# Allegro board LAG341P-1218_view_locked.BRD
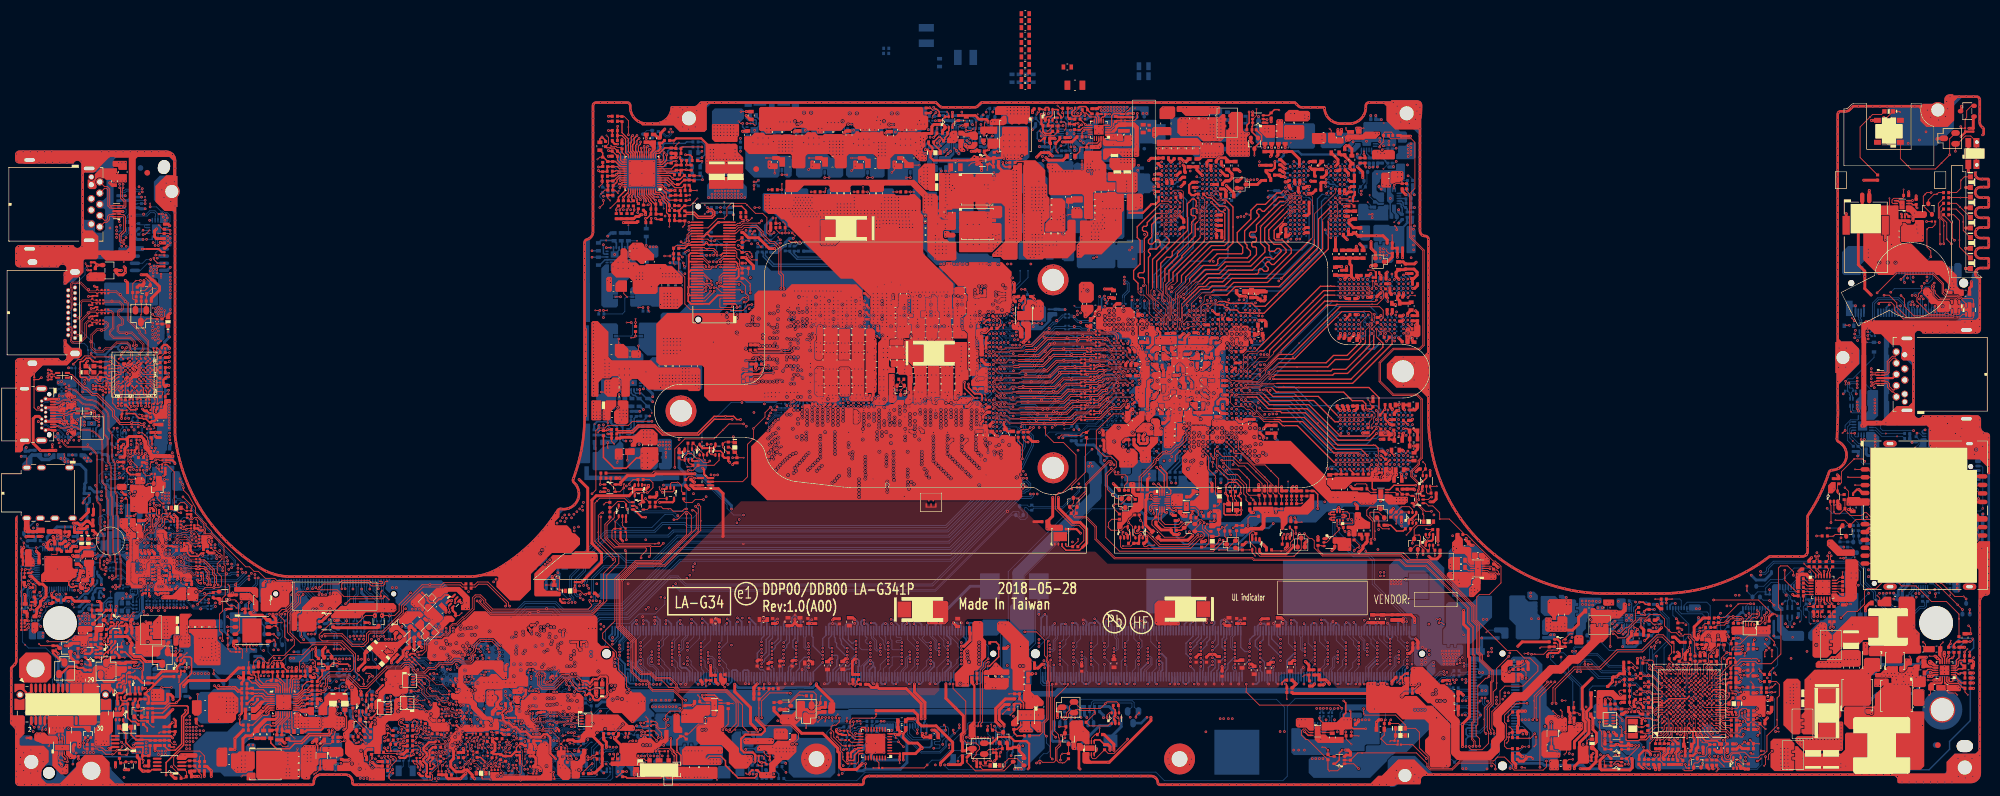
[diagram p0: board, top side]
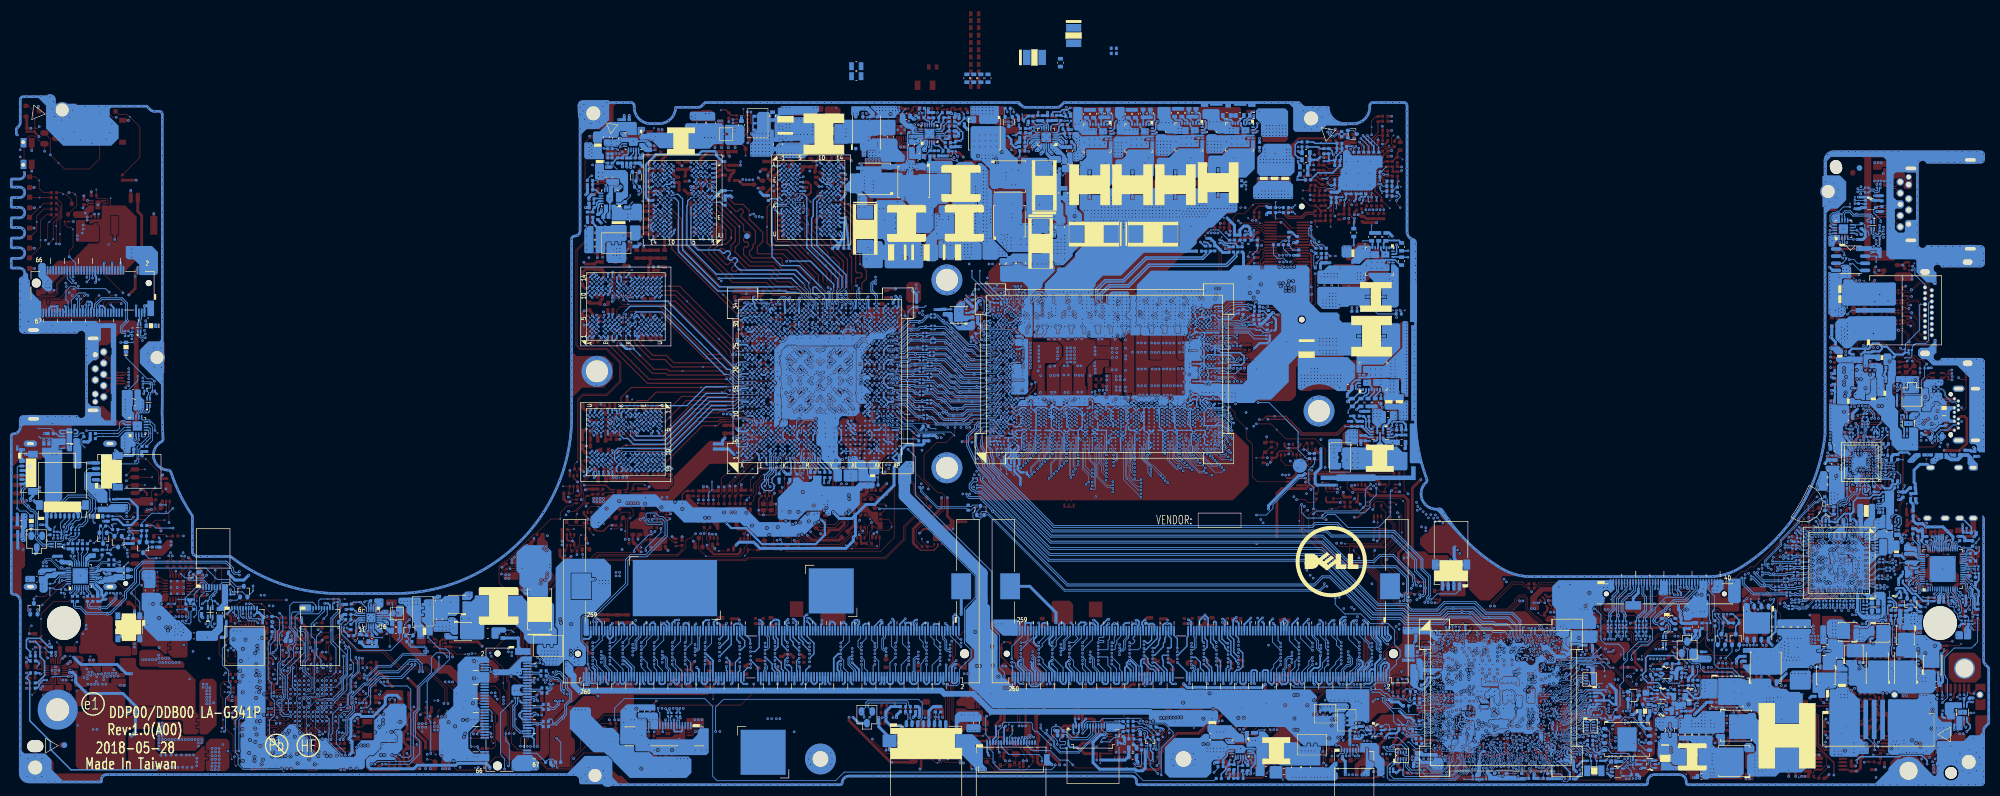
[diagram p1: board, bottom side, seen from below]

No outline. copper layers: TOP, GND1, IN1, IN2, GND2, IN3, IN4, VCC, IN5, IN6, GND3, BOTTOM. Coordinates in mm from the lowest, leftmost part position.

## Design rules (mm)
net group DDI1: nets DDI1_DDPB_CTRLCLK DDI1_DDPB_CTRLDAT
net group DDI2: nets DDI2_DDPC_CTRLCLK DDI2_DDPC_CTRLDAT
net group GPU-SENSE: nets VCCSENSE_VGA VSSSENSE_VGA
net group HDMI-DDC: nets DDC_CLK_HDMI DDC_DAT_HDMI
net group LPC_CLK: nets PCI_CLK_LPC1 PCI_CLK_LPC1_R
net group SENSE: nets VCC_SENSE VSS_SENSE
net group TBT_RX/TX: nets TBT_USB3_TX0_N_C TBT_USB3_TX1_N_C
net group UART: nets UART2_RXD UART2_TXD
net group USB3.0-TBTA: nets TBTA_CC1 TBTA_CC2
net group ASY: nets CPU_TRIGGER CPU_TRIGGER_R DGPU_HOLD_RST# H_CATERR# H_CPUPWRGD H_PM_DOWN H_PM_DOWN_R H_PM_SYNC H_PM_SYNC_R H_PROCHOT# H_PROCHOT#_EC H_PROCHOT#_R H_THERMTRIP# H_THERMTRIP#_R H_VCCST_PWRGD INTRUDER# LPC_PD# PCH_DPWROK_EC PCH_DPWROK_R PCH_PCIE_WAKE# PCH_PWROK PCH_RSMRST# PCH_SYS_PWROK_XDP PCH_TRIGGER PCH_TRIGGER_R PLTRST_CPU# PWRBTN#_XDP SIO_PWRBTN# SIO_RCIN# SYS_PWROK SYS_RESET# VCCST_PWRGD_CPU XDP_BPM#0 XDP_BPM#1
net group AUDIO: nets HPOUT_D_L_C HPOUT_D_R_C HPOUT_L HPOUT_L_R1 HPOUT_R HPOUT_R_R2 LINE1-VREFO LINE1_L LINE1_L_C LINE1_R LINE1_R_C MIC1-VREFO_L MIC1-VREFO_R RING2 RING2_L SLEEVE SLEEVE_L
net group DDR_CLK: nets M_CLK_DDR0 M_CLK_DDR1 M_CLK_DDR2 M_CLK_DDR3 M_CLK_DDR#0 M_CLK_DDR#1 M_CLK_DDR#2 M_CLK_DDR#3
net group DDR_DQS: nets DDR_A_DQS0 DDR_A_DQS1 DDR_A_DQS2 DDR_A_DQS3 DDR_A_DQS4 DDR_A_DQS5 DDR_A_DQS6 DDR_A_DQS7 DDR_A_DQS#0 DDR_A_DQS#1 DDR_A_DQS#2 DDR_A_DQS#3 DDR_A_DQS#4 DDR_A_DQS#5 DDR_A_DQS#6 DDR_A_DQS#7 DDR_B_DQS0 DDR_B_DQS1 DDR_B_DQS2 DDR_B_DQS3 DDR_B_DQS4 DDR_B_DQS5 DDR_B_DQS6 DDR_B_DQS7 DDR_B_DQS#0 DDR_B_DQS#1 DDR_B_DQS#2 DDR_B_DQS#3 DDR_B_DQS#4 DDR_B_DQS#5 DDR_B_DQS#6 DDR_B_DQS#7
net group DDRA_ADD: nets DDR_A_ACT# DDR_A_ALERT# DDR_A_BG0 DDR_A_BG1 DDR_A_BS0 DDR_A_BS1 DDR_A_CAS# DDR_A_MA0 DDR_A_MA1 DDR_A_MA2 DDR_A_MA3 DDR_A_MA4 DDR_A_MA5 DDR_A_MA6 DDR_A_MA7 DDR_A_MA8 DDR_A_MA9 DDR_A_MA10 DDR_A_MA11 DDR_A_MA12 DDR_A_MA13 DDR_A_PAR DDR_A_RAS# DDR_A_WE#
net group DDRA_CTRL: nets DDR_CKE0_DIMMA DDR_CKE1_DIMMA DDR_CS0_DIMMA# DDR_CS1_DIMMA# M_ODT0 M_ODT1
net group DDRA_D0: nets DDR_A_D0 DDR_A_D1 DDR_A_D2 DDR_A_D3 DDR_A_D4 DDR_A_D5 DDR_A_D6 DDR_A_D7
net group DDRA_D1: nets DDR_A_D8 DDR_A_D9 DDR_A_D10 DDR_A_D11 DDR_A_D12 DDR_A_D13 DDR_A_D14 DDR_A_D15
net group DDRA_D2: nets DDR_A_D16 DDR_A_D17 DDR_A_D18 DDR_A_D19 DDR_A_D20 DDR_A_D21 DDR_A_D22 DDR_A_D23
net group DDRA_D3: nets DDR_A_D24 DDR_A_D25 DDR_A_D26 DDR_A_D27 DDR_A_D28 DDR_A_D29 DDR_A_D30 DDR_A_D31
net group DDRA_D4: nets DDR_A_D32 DDR_A_D33 DDR_A_D34 DDR_A_D35 DDR_A_D36 DDR_A_D37 DDR_A_D38 DDR_A_D39
net group DDRA_D5: nets DDR_A_D40 DDR_A_D41 DDR_A_D42 DDR_A_D43 DDR_A_D44 DDR_A_D45 DDR_A_D46 DDR_A_D47
net group DDRA_D6: nets DDR_A_D48 DDR_A_D49 DDR_A_D50 DDR_A_D51 DDR_A_D52 DDR_A_D53 DDR_A_D54 DDR_A_D55
net group DDRA_D7: nets DDR_A_D56 DDR_A_D57 DDR_A_D58 DDR_A_D59 DDR_A_D60 DDR_A_D61 DDR_A_D62 DDR_A_D63
net group DDRB_ADD: nets DDR_B_ACT# DDR_B_ALERT# DDR_B_BG0 DDR_B_BG1 DDR_B_BS0 DDR_B_BS1 DDR_B_CAS# DDR_B_MA0 DDR_B_MA1 DDR_B_MA2 DDR_B_MA3 DDR_B_MA4 DDR_B_MA5 DDR_B_MA6 DDR_B_MA7 DDR_B_MA8 DDR_B_MA9 DDR_B_MA10 DDR_B_MA11 DDR_B_MA12 DDR_B_MA13 DDR_B_PAR DDR_B_RAS# DDR_B_WE#
net group DDRB_CTRL: nets DDR_CKE2_DIMMB DDR_CKE3_DIMMB DDR_CS2_DIMMB# DDR_CS3_DIMMB# M_ODT2 M_ODT3
net group DDRB_D0: nets DDR_B_D0 DDR_B_D1 DDR_B_D2 DDR_B_D3 DDR_B_D4 DDR_B_D5 DDR_B_D6 DDR_B_D7
net group DDRB_D1: nets DDR_B_D8 DDR_B_D9 DDR_B_D10 DDR_B_D11 DDR_B_D12 DDR_B_D13 DDR_B_D14 DDR_B_D15
net group DDRB_D2: nets DDR_B_D16 DDR_B_D17 DDR_B_D18 DDR_B_D19 DDR_B_D20 DDR_B_D21 DDR_B_D22 DDR_B_D23
net group DDRB_D3: nets DDR_B_D24 DDR_B_D25 DDR_B_D26 DDR_B_D27 DDR_B_D28 DDR_B_D29 DDR_B_D30 DDR_B_D31
net group DDRB_D4: nets DDR_B_D32 DDR_B_D33 DDR_B_D34 DDR_B_D35 DDR_B_D36 DDR_B_D37 DDR_B_D38 DDR_B_D39
net group DDRB_D5: nets DDR_B_D40 DDR_B_D41 DDR_B_D42 DDR_B_D43 DDR_B_D44 DDR_B_D45 DDR_B_D46 DDR_B_D47
net group DDRB_D6: nets DDR_B_D48 DDR_B_D49 DDR_B_D50 DDR_B_D51 DDR_B_D52 DDR_B_D53 DDR_B_D54 DDR_B_D55
net group DDRB_D7: nets DDR_B_D56 DDR_B_D57 DDR_B_D58 DDR_B_D59 DDR_B_D60 DDR_B_D61 DDR_B_D62 DDR_B_D63
net group DMI: nets DMI_CRX_PTX_N0 DMI_CRX_PTX_N1 DMI_CRX_PTX_N2 DMI_CRX_PTX_N3 DMI_CRX_PTX_P0 DMI_CRX_PTX_P1 DMI_CRX_PTX_P2 DMI_CRX_PTX_P3 DMI_CTX_PRX_N0 DMI_CTX_PRX_N1 DMI_CTX_PRX_N2 DMI_CTX_PRX_N3 DMI_CTX_PRX_P0 DMI_CTX_PRX_P1 DMI_CTX_PRX_P2 DMI_CTX_PRX_P3
net group EDP: nets EDP_AUXN EDP_AUXN_C EDP_AUXN_R EDP_AUXP EDP_AUXP_C EDP_AUXP_R EDP_HPD_S EDP_TXN0 EDP_TXN0_C EDP_TXN0_R EDP_TXN1 EDP_TXN1_C EDP_TXN1_R EDP_TXN2 EDP_TXN2_C EDP_TXN2_R EDP_TXN3 EDP_TXN3_C EDP_TXN3_R EDP_TXP0 EDP_TXP0_C EDP_TXP0_R EDP_TXP1 EDP_TXP1_C EDP_TXP1_R EDP_TXP2 EDP_TXP2_C EDP_TXP2_R EDP_TXP3 EDP_TXP3_C EDP_TXP3_R
net group ESPI: nets ESPI_ALERT# ESPI_CLK ESPI_CS# ESPI_IO0_R ESPI_IO1_R ESPI_IO2_R ESPI_IO3_R
net group FBA_CLK: nets FBA_CLK0 FBA_CLK0# FBA_CLK1 FBA_CLK1#
net group FBA_CMD: nets FBA_ABI#_H FBA_ABI#_L FBA_CAS#_H FBA_CAS#_L FBA_CKE_H FBA_CKE_L FBA_CS#_H FBA_CS#_L FBA_MA0_MA10_H FBA_MA0_MA10_L FBA_MA1_MA9_H FBA_MA1_MA9_L FBA_MA2_BA0_H FBA_MA2_BA0_L FBA_MA3_BA3_H FBA_MA3_BA3_L FBA_MA4_BA2_H FBA_MA4_BA2_L FBA_MA5_BA1_H FBA_MA5_BA1_L FBA_MA6_MA11_H FBA_MA6_MA11_L FBA_MA7_MA8_H FBA_MA7_MA8_L FBA_MA12_RFU_H FBA_MA12_RFU_L FBA_RAS#_H FBA_RAS#_L FBA_RST#_H FBA_RST#_L FBA_WE#_H FBA_WE#_L
net group FBA_D0: nets FBA_D0 FBA_D1 FBA_D2 FBA_D3 FBA_D4 FBA_D5 FBA_D6 FBA_D7
net group FBA_D1: nets FBA_D8 FBA_D9 FBA_D10 FBA_D11 FBA_D12 FBA_D13 FBA_D14 FBA_D15
net group FBA_D2: nets FBA_D16 FBA_D17 FBA_D18 FBA_D19 FBA_D20 FBA_D21 FBA_D22 FBA_D23
net group FBA_D3: nets FBA_D24 FBA_D25 FBA_D26 FBA_D27 FBA_D28 FBA_D29 FBA_D30 FBA_D31
net group FBA_D4: nets FBA_D32 FBA_D33 FBA_D34 FBA_D35 FBA_D36 FBA_D37 FBA_D38 FBA_D39
net group FBA_D5: nets FBA_D40 FBA_D41 FBA_D42 FBA_D43 FBA_D44 FBA_D45 FBA_D46 FBA_D47
net group FBA_D6: nets FBA_D48 FBA_D49 FBA_D50 FBA_D51 FBA_D52 FBA_D53 FBA_D54 FBA_D55
net group FBA_D7: nets FBA_D56 FBA_D57 FBA_D58 FBA_D59 FBA_D60 FBA_D61 FBA_D62 FBA_D63
net group FBA_DBI: nets FBA_DBI0# FBA_DBI1# FBA_DBI2# FBA_DBI3# FBA_DBI4# FBA_DBI5# FBA_DBI6# FBA_DBI7#
net group FBA_EDC: nets FBA_EDC0 FBA_EDC1 FBA_EDC2 FBA_EDC3 FBA_EDC4 FBA_EDC5 FBA_EDC6 FBA_EDC7
net group FBA_WCK: nets FBA_WCK0 FBA_WCK0_N FBA_WCK1 FBA_WCK1_N FBA_WCK2 FBA_WCK2_N FBA_WCK3 FBA_WCK3_N
net group FBC_CLK: nets FBC_CLK0 FBC_CLK0# FBC_CLK1 FBC_CLK1#
net group FBC_CMD: nets FBC_ABI#_H FBC_ABI#_L FBC_CAS#_H FBC_CAS#_L FBC_CKE_H FBC_CKE_L FBC_CS#_H FBC_CS#_L FBC_MA0_MA10_H FBC_MA0_MA10_L FBC_MA1_MA9_H FBC_MA1_MA9_L FBC_MA2_BA0_H FBC_MA2_BA0_L FBC_MA3_BA3_H FBC_MA3_BA3_L FBC_MA4_BA2_H FBC_MA4_BA2_L FBC_MA5_BA1_H FBC_MA5_BA1_L FBC_MA6_MA11_H FBC_MA6_MA11_L FBC_MA7_MA8_H FBC_MA7_MA8_L FBC_MA12_RFU_H FBC_MA12_RFU_L FBC_RAS#_H FBC_RAS#_L FBC_RST#_H FBC_RST#_L FBC_WE#_H FBC_WE#_L
net group FBC_D0: nets FBC_D0 FBC_D1 FBC_D2 FBC_D3 FBC_D4 FBC_D5 FBC_D6 FBC_D7
net group FBC_D1: nets FBC_D8 FBC_D9 FBC_D10 FBC_D11 FBC_D12 FBC_D13 FBC_D14 FBC_D15
net group FBC_D2: nets FBC_D16 FBC_D17 FBC_D18 FBC_D19 FBC_D20 FBC_D21 FBC_D22 FBC_D23
net group FBC_D3: nets FBC_D24 FBC_D25 FBC_D26 FBC_D27 FBC_D28 FBC_D29 FBC_D30 FBC_D31
net group FBC_D4: nets FBC_D32 FBC_D33 FBC_D34 FBC_D35 FBC_D36 FBC_D37 FBC_D38 FBC_D39
net group FBC_D5: nets FBC_D40 FBC_D41 FBC_D42 FBC_D43 FBC_D44 FBC_D45 FBC_D46 FBC_D47
net group FBC_D6: nets FBC_D48 FBC_D49 FBC_D50 FBC_D51 FBC_D52 FBC_D53 FBC_D54 FBC_D55
net group FBC_D7: nets FBC_D56 FBC_D57 FBC_D58 FBC_D59 FBC_D60 FBC_D61 FBC_D62 FBC_D63
net group FBC_DBI: nets FBC_DBI0# FBC_DBI1# FBC_DBI2# FBC_DBI3# FBC_DBI4# FBC_DBI5# FBC_DBI6# FBC_DBI7#
net group FBC_EDC: nets FBC_EDC0 FBC_EDC1 FBC_EDC2 FBC_EDC3 FBC_EDC4 FBC_EDC5 FBC_EDC6 FBC_EDC7
net group FBC_WCK: nets FBC_WCK0 FBC_WCK0_N FBC_WCK1 FBC_WCK1_N FBC_WCK2 FBC_WCK2_N FBC_WCK3 FBC_WCK3_N
net group GPU-CORESENSE: nets FBVDDQ_SENSE GNDS_SENSE_VGA N128727776 N128727796 VDDS_SENSE_VGA
net group HDA: nets AUD_AZA_CPU_SCLK AUD_AZA_CPU_SCLK_R AUD_AZA_CPU_SDI AUD_AZA_CPU_SDI_R AUD_AZA_CPU_SDO AUD_AZA_CPU_SDO_R HDA_BITCLK HDA_BITCLK_AUDIO HDA_RST# HDA_SDIN0 HDA_SDIN0_AUDIO HDA_SDOUT HDA_SDOUT_AUDIO HDA_SYNC HDA_SYNC_AUDIO I2S_BCLK I2S_IN I2S_LRCK I2S_MCLK I2S_OUT I2S_RST_AUDIO# I2S_RST_AUDIO#_R I2S_SDIN0_AUDIO_R
net group HDMI: nets HDMI_CLKN HDMI_CLKP HDMI_R_CLKN HDMI_R_CLKP HDMI_R_TX_N0 HDMI_R_TX_N1 HDMI_R_TX_N2 HDMI_R_TX_P0 HDMI_R_TX_P1 HDMI_R_TX_P2 HDMI_TX_N0 HDMI_TX_N1 HDMI_TX_N2 HDMI_TX_P0 HDMI_TX_P1 HDMI_TX_P2
net group I2C: nets BC_CLK_ECE1117 BC_DAT_ECE1117 CLK_TP_SIO DAT_TP_SIO DMIC_CLK_CODEC DMIC_CLK_CODEC_C DMIC_DAT_CODEC DMIC_DAT_CODEC_C EDP_PANEL_CLK EDP_PANEL_DAT I2C0_SCK_DSP I2C0_SCK_TS I2C0_SCK_TS_R I2C0_SDA_DSP I2C0_SDA_TS I2C0_SDA_TS_R I2C1_SCK_TP I2C1_SCK_TP_C I2C1_SDA_TP I2C1_SDA_TP_C I2CB_SCL I2CB_SDA MSCLK MSCLK_R MSDATA MSDATA_R TBT_I2C_CLK TBT_I2C_CLK_R TBT_I2C_DATA TBT_I2C_DATA_R USBC_MCP23008_SMBCLK USBC_MCP23008_SMBDAT VGA_EDID_CLK VGA_EDID_DATA
net group N17-XTL: nets XTAL_OUT XTALIN XTALOUT XTALSSIN
net group PCIE: nets PCIE_PRX_C_DTX_N5 PCIE_PRX_C_DTX_P5 PCIE_PRX_DTX_N1 PCIE_PRX_DTX_N5 PCIE_PRX_DTX_N09 PCIE_PRX_DTX_N10 PCIE_PRX_DTX_P1 PCIE_PRX_DTX_P5 PCIE_PRX_DTX_P09 PCIE_PRX_DTX_P10 PCIE_PTX_C_DRX_N1 PCIE_PTX_C_DRX_N5 PCIE_PTX_C_DRX_N09 PCIE_PTX_C_DRX_N10 PCIE_PTX_C_DRX_N11 PCIE_PTX_C_DRX_P1 PCIE_PTX_C_DRX_P5 PCIE_PTX_C_DRX_P09 PCIE_PTX_C_DRX_P10 PCIE_PTX_C_DRX_P11 PCIE_PTX_DRX_N1 PCIE_PTX_DRX_N5 PCIE_PTX_DRX_N09 PCIE_PTX_DRX_N10 PCIE_PTX_DRX_N11 PCIE_PTX_DRX_P1 PCIE_PTX_DRX_P5 PCIE_PTX_DRX_P09 PCIE_PTX_DRX_P10 PCIE_PTX_DRX_P11
net group PCIE-AR: nets PCIE_PRX_C_TTX_N17 PCIE_PRX_C_TTX_N18 PCIE_PRX_C_TTX_N19 PCIE_PRX_C_TTX_N20 PCIE_PRX_C_TTX_P17 PCIE_PRX_C_TTX_P18 PCIE_PRX_C_TTX_P19 PCIE_PRX_C_TTX_P20 PCIE_PRX_TTX_N17 PCIE_PRX_TTX_N18 PCIE_PRX_TTX_N19 PCIE_PRX_TTX_N20 PCIE_PRX_TTX_P17 PCIE_PRX_TTX_P18 PCIE_PRX_TTX_P19 PCIE_PRX_TTX_P20 PCIE_PTX_C_TRX_N17 PCIE_PTX_C_TRX_N18 PCIE_PTX_C_TRX_N19 PCIE_PTX_C_TRX_N20 PCIE_PTX_C_TRX_P17 PCIE_PTX_C_TRX_P18 PCIE_PTX_C_TRX_P19 PCIE_PTX_C_TRX_P20 PCIE_PTX_TRX_N17 PCIE_PTX_TRX_N18 PCIE_PTX_TRX_N19 PCIE_PTX_TRX_N20 PCIE_PTX_TRX_P17 PCIE_PTX_TRX_P18 PCIE_PTX_TRX_P19 PCIE_PTX_TRX_P20
net group PECI: nets H_PECI H_PECI_R PCH_PECI PCIE_WAKE#
net group PEG: nets PEG_GTX_C_HRX_N0 PEG_GTX_C_HRX_N1 PEG_GTX_C_HRX_N2 PEG_GTX_C_HRX_N3 PEG_GTX_C_HRX_N4 PEG_GTX_C_HRX_N5 PEG_GTX_C_HRX_N6 PEG_GTX_C_HRX_N7 PEG_GTX_C_HRX_N8 PEG_GTX_C_HRX_N9 PEG_GTX_C_HRX_N10 PEG_GTX_C_HRX_N11 PEG_GTX_C_HRX_N12 PEG_GTX_C_HRX_N13 PEG_GTX_C_HRX_N14 PEG_GTX_C_HRX_N15 PEG_GTX_C_HRX_P0 PEG_GTX_C_HRX_P1 PEG_GTX_C_HRX_P2 PEG_GTX_C_HRX_P3 PEG_GTX_C_HRX_P4 PEG_GTX_C_HRX_P5 PEG_GTX_C_HRX_P6 PEG_GTX_C_HRX_P7 PEG_GTX_C_HRX_P8 PEG_GTX_C_HRX_P9 PEG_GTX_C_HRX_P10 PEG_GTX_C_HRX_P11 PEG_GTX_C_HRX_P12 PEG_GTX_C_HRX_P13 PEG_GTX_C_HRX_P14 PEG_GTX_C_HRX_P15 PEG_GTX_HRX_N0 PEG_GTX_HRX_N1 PEG_GTX_HRX_N2 PEG_GTX_HRX_N3 PEG_GTX_HRX_N4 PEG_GTX_HRX_N5 PEG_GTX_HRX_N6 PEG_GTX_HRX_N7 PEG_GTX_HRX_N8 PEG_GTX_HRX_N9 PEG_GTX_HRX_N10 PEG_GTX_HRX_N11 PEG_GTX_HRX_N12 PEG_GTX_HRX_N13 PEG_GTX_HRX_N14 PEG_GTX_HRX_N15 PEG_GTX_HRX_P0 PEG_GTX_HRX_P1 PEG_GTX_HRX_P2 PEG_GTX_HRX_P3 PEG_GTX_HRX_P4 PEG_GTX_HRX_P5 PEG_GTX_HRX_P6 PEG_GTX_HRX_P7 PEG_GTX_HRX_P8 PEG_GTX_HRX_P9 PEG_GTX_HRX_P10 PEG_GTX_HRX_P11 PEG_GTX_HRX_P12 PEG_GTX_HRX_P13 PEG_GTX_HRX_P14 PEG_GTX_HRX_P15 PEG_HTX_C_GRX_N0 PEG_HTX_C_GRX_N1 PEG_HTX_C_GRX_N2 PEG_HTX_C_GRX_N3 PEG_HTX_C_GRX_N4 PEG_HTX_C_GRX_N5 PEG_HTX_C_GRX_N6 PEG_HTX_C_GRX_N7 PEG_HTX_C_GRX_N8 PEG_HTX_C_GRX_N9 PEG_HTX_C_GRX_N10 PEG_HTX_C_GRX_N11 PEG_HTX_C_GRX_N12 PEG_HTX_C_GRX_N13 PEG_HTX_C_GRX_N14 PEG_HTX_C_GRX_N15 PEG_HTX_C_GRX_P0 PEG_HTX_C_GRX_P1 PEG_HTX_C_GRX_P2 PEG_HTX_C_GRX_P3 PEG_HTX_C_GRX_P4 PEG_HTX_C_GRX_P5 PEG_HTX_C_GRX_P6 PEG_HTX_C_GRX_P7 PEG_HTX_C_GRX_P8 PEG_HTX_C_GRX_P9 PEG_HTX_C_GRX_P10 PEG_HTX_C_GRX_P11 PEG_HTX_C_GRX_P12 PEG_HTX_C_GRX_P13 PEG_HTX_C_GRX_P14 PEG_HTX_C_GRX_P15 PEG_HTX_GRX_N0 PEG_HTX_GRX_N1 PEG_HTX_GRX_N2 PEG_HTX_GRX_N3 PEG_HTX_GRX_N4 PEG_HTX_GRX_N5 PEG_HTX_GRX_N6 PEG_HTX_GRX_N7 PEG_HTX_GRX_N8 PEG_HTX_GRX_N9 PEG_HTX_GRX_N10 PEG_HTX_GRX_N11 PEG_HTX_GRX_N12 PEG_HTX_GRX_N13 PEG_HTX_GRX_N14 PEG_HTX_GRX_N15 PEG_HTX_GRX_P0 PEG_HTX_GRX_P1 PEG_HTX_GRX_P2 PEG_HTX_GRX_P3 PEG_HTX_GRX_P4 PEG_HTX_GRX_P5 PEG_HTX_GRX_P6 PEG_HTX_GRX_P7 PEG_HTX_GRX_P8 PEG_HTX_GRX_P9 PEG_HTX_GRX_P10 PEG_HTX_GRX_P11 PEG_HTX_GRX_P12 PEG_HTX_GRX_P13 PEG_HTX_GRX_P14 PEG_HTX_GRX_P15
net group PLATFORM CLK: nets CLK_PCIE_N3 CLK_PCIE_N4 CLK_PCIE_N5 CLK_PCIE_N6 CLK_PCIE_N7 CLK_PCIE_P3 CLK_PCIE_P4 CLK_PCIE_P5 CLK_PCIE_P6 CLK_PCIE_P7 CPU_24MHZ_N CPU_24MHZ_P PCH_CPU_BCLK_N PCH_CPU_BCLK_P PCH_CPU_PCIBCLK_N PCH_CPU_PCIBCLK_P PCH_XDP_CLK_N PCH_XDP_CLK_P
net group PLATFORM CLOCK-SE: nets XCLK_BIASREF XTAL24_IN XTAL24_IN_R XTAL24_OUT XTAL24_OUT_R
net group PWM: nets BIA_PWM_EC BIA_PWM_EC_R BIA_PWM_PCH INV_PWM PWM_FAN1 PWM_FAN2 TACH_FAN1 TACH_FAN2
net group RTC: nets 32KHZ_OUT MEC_XTAL1 MEC_XTAL2 MEC_XTAL2_R PCH_RTCRST# PCH_RTCX1 PCH_RTCX2 PCH_SRTCRST# SUSCLK SUSCLK_R
net group SATA: nets PCIE_PRX_DTX_N11 PCIE_PRX_DTX_P11 SATA_PRX_C_DTX_N2 SATA_PRX_C_DTX_P2 SATA_PRX_DTX_N1A SATA_PRX_DTX_N2 SATA_PRX_DTX_P1A SATA_PRX_DTX_P2 SATA_PTX_C_DRX_N1A SATA_PTX_C_DRX_N2 SATA_PTX_C_DRX_P1A SATA_PTX_C_DRX_P2 SATA_PTX_DRX_N1A SATA_PTX_DRX_N2 SATA_PTX_DRX_P1A SATA_PTX_DRX_P2
net group SD: nets SD_CD# SD_CLK SD_CLK_R SD_CMD SD_CMD_R SD_D2 SD_D2_R SD_D3 SD_D3_R SD_REG2
net group SD4.0: nets SD_LN0_M SD_LN0_P SD_LN1_M SD_LN1_P SD_RCLK_M SD_RCLK_M_R SD_RCLK_P SD_RCLK_P_R
net group SMB: nets AUDIO_AMP_SMBCLK AUDIO_AMP_SMBDAT CLINK_CLK CLINK_DATA DOCK_TNY_SMB_CLK DOCK_TNY_SMB_DAT EC_SMB_CK2_PX EC_SMB_DA2_PX GPU_SMBCLK GPU_SMBDAT MEM_SMBCLK MEM_SMBDATA PBAT_CHARGER_SMBCLK PBAT_CHARGER_SMBDAT PCH_DMIC_CLK PCH_DMIC_CLK_R PCH_DMIC_DAT PCH_DMIC_DAT_R PCH_SMBCLK PCH_SMBDATA SML0_SMBCLK SML0_SMBDATA SML1_SMBCLK SML1_SMBDAT TBT_LSRX TBT_LSTX TBTA_DEBUG1 TBTA_DEBUG2 TBTA_DEBUG3_LSTX TBTA_DEBUG4_LSRX UPD_SMBCLK UPD_SMBDAT
net group SPI: nets DTH_SPI_CK_OUT DTH_SPI_CS DTH_SPI_D_IN DTH_SPI_D_OUT DTH_SPI_WR_PROT PCH_SPI_CLK PCH_SPI_CLK_R PCH_SPI_CLK_TPM PCH_SPI_CLK_TPM_R PCH_SPI_CS#0 PCH_SPI_CS#1 PCH_SPI_CS#2 PCH_SPI_CS#2_R PCH_SPI_HOLD# PCH_SPI_HOLD#_R PCH_SPI_SI PCH_SPI_SI_R PCH_SPI_SI_TPM PCH_SPI_SI_TPM_R PCH_SPI_SO PCH_SPI_SO_R PCH_SPI_SO_TPM PCH_SPI_SO_TPM_R PCH_SPI_WP# PCH_SPI_WP#_R TBT_ROM_CLK TBT_ROM_CS# TBT_ROM_DI TBT_ROM_DO TBT_ROM_HOLD# TBT_ROM_WP#
net group SVID: nets VR_SVID_ALERT# VR_SVID_ALERT#_R VR_SVID_CLK VR_SVID_DATA
net group TBT-AR: nets CPU_DP3_AUXN CPU_DP3_AUXN_C CPU_DP3_AUXN_R CPU_DP3_AUXP CPU_DP3_AUXP_C CPU_DP3_AUXP_R CPU_DP3_N0 CPU_DP3_N0_C CPU_DP3_N1 CPU_DP3_N1_C CPU_DP3_N2 CPU_DP3_N2_C CPU_DP3_N3 CPU_DP3_N3_C CPU_DP3_P0 CPU_DP3_P0_C CPU_DP3_P1 CPU_DP3_P1_C CPU_DP3_P2 CPU_DP3_P2_C CPU_DP3_P3 CPU_DP3_P3_C
net group TBT-DP-AR: nets CPU_DP2_AUXN CPU_DP2_AUXN_C CPU_DP2_AUXP CPU_DP2_AUXP_C CPU_DP2_N0 CPU_DP2_N0_C CPU_DP2_N1 CPU_DP2_N1_C CPU_DP2_N2 CPU_DP2_N2_C CPU_DP2_N3 CPU_DP2_N3_C CPU_DP2_P0 CPU_DP2_P0_C CPU_DP2_P1 CPU_DP2_P1_C CPU_DP2_P2 CPU_DP2_P2_C CPU_DP2_P3 CPU_DP2_P3_C
net group TBT-DP-PS1752: nets CPU_DP1_AUXN CPU_DP1_AUXN_C CPU_DP1_AUXP CPU_DP1_AUXP_C CPU_DP1_N0 CPU_DP1_N0_C CPU_DP1_N1 CPU_DP1_N1_C CPU_DP1_N2 CPU_DP1_N2_C CPU_DP1_N3 CPU_DP1_N3_C CPU_DP1_P0 CPU_DP1_P0_C CPU_DP1_P1 CPU_DP1_P1_C CPU_DP1_P2 CPU_DP1_P2_C CPU_DP1_P3 CPU_DP1_P3_C
net group TBT-JUSBC: nets TBT_USB2_D+ TBT_USB2_D- TBT_USB3_RX0_N TBT_USB3_RX0_N_R TBT_USB3_RX0_P_R TBT_USB3_RX1_N TBT_USB3_RX1_N_R TBT_USB3_RX1_P TBT_USB3_RX1_P_R TBT_USB3_TX0_N TBT_USB3_TX0_P TBT_USB3_TX0_P_C TBT_USB3_TX1_N TBT_USB3_TX1_P TBT_USB3_TX1_P_C TBTA_AUX_N TBTA_AUX_N_C TBTA_AUX_P TBTA_AUX_P_C TBTA_BOT_C_N TBTA_BOT_C_P TBTA_BOT_N TBTA_BOT_P TBTA_PD_SBU1 TBTA_PD_SBU2 TBTA_SBU1 TBTA_SBU2 TBTA_TOP_C_N TBTA_TOP_C_P TBTA_TOP_N TBTA_TOP_P USB20_N5 USB20_N5_R USB20_P5 USB20_P5_R
net group THERMAL DIODE: nets REM_DIODE1_N REM_DIODE1_P REM_DIODE2_N REM_DIODE2_P REM_DIODE3_N REM_DIODE3_P REM_DIODE4_N REM_DIODE4_P
net group USB2.0: nets CHR_USB20_N1 CHR_USB20_N1_R CHR_USB20_N2 CHR_USB20_N2_R CHR_USB20_P1 CHR_USB20_P1_R CHR_USB20_P2 CHR_USB20_P2_R USB20_FP_N7_CONN USB20_FP_P7_CONN USB20_N1 USB20_N2 USB20_N4 USB20_N4_R USB20_N7 USB20_N9 USB20_N9_R USB20_N12 USB20_N12_R USB20_P1 USB20_P2 USB20_P4 USB20_P4_R USB20_P7 USB20_P9 USB20_P9_R USB20_P12 USB20_P12_R
net group USB3.1: nets USB3_PRX_C_RD_DTX_N1 USB3_PRX_C_RD_DTX_P1 USB3_PRX_DTX_N1 USB3_PRX_DTX_N2 USB3_PRX_DTX_P1 USB3_PRX_DTX_P2 USB3_PRX_L_DTX_N1 USB3_PRX_L_DTX_P1 USB3_PRX_RD_DTX_N1 USB3_PRX_RD_DTX_P1 USB3_PTX_C_DRX_N1 USB3_PTX_C_DRX_P1 USB3_PTX_C_RD_DRX_N1 USB3_PTX_C_RD_DRX_P1 USB3_PTX_DRX_N1 USB3_PTX_DRX_N2 USB3_PTX_DRX_P1 USB3_PTX_DRX_P2 USB3_PTX_L_DRX_N1 USB3_PTX_L_DRX_P1 USB3_PTX_RD_DRX_N1 USB3_PTX_RD_DRX_P1
net group X-TAL: nets DTH_XTLI DTH_XTLO XTAL_25_IN XTAL_25_IN_R XTAL_25_OUT XTAL_25_OUT_R
nets with their own width: min track width 0.203; nets VCC1V8A_TBTA_LDO
nets with their own width: min track width 0.254; nets GPU_CORE_PG N132908405 N132908425 N132908471 N132908575 N132908582 NVVDD_EN NVVDDS_EN VCC_3V3_PCIE VCC_3V3_USB2
nets with their own width: min track width 0.381; nets +PEX_PLL_HVDD +PEX_SVDD_3V3 N130500830
nets with their own width: min track width 0.406; nets +FBA_VREFC0
nets with their own width: min track width 0.508; nets +0.6VS +0.6VSP +1.2V_DDR +1.2V_MEN_P +1.2V_PWROK +1.2V_VCCPLL_OC +1.35VSDGPU +1V_PCH +1V_PCH_AZPLL +1V_PCH_PRIM +1V_VCCDSW +1VALW +1VSP +3V_PCH +3V_PCH_AZIO +3V_PCH_DSW +3V_ROM +3V_TBT +3VA_TBT +3VA_TBT_LC +3VALW +3VALW_5105 +3VALWP +3VLP +3VS +3VS_CAM +3VS_CR +3VS_DTH +3VS_FFS +3VS_TP +3VS_TPM_VSB +3VS_TS +3VS_WLAN +5V_CHGUSB_1 +5V_CHGUSB_2 +5VALW +5VALWP +5VS +AC_IN +DC_IN +DC_IN_SS +GPU_CORE +GPU_CORE_VDDS +ODR_PWR +RTC_CELL_VBAT +RTCBATT +RTCVCC +RTCVCC_R +SD_VDD2 +SDC_IN +V_DDR_REF +V_DDR_REFA +V_DDR_REFA_R +V_DDR_REFB +V_DDR_REFB_R +VBUS_1 +VBUS_DC_SS +VCC0V9_PCIE +VCC0V9_USB +VCC_CORE +VCCGT +VCCIO +VCCSA +VCCST +VCCSTG +VGA_B+ +VLDOIN_1.2V +VR_CAP AGND B+ B++ DGPU_PEX_RST# DTH_VDD33 DTH_VDDA12 DTH_VDDRX12 DTH_VDDTX12 EDP_COMP GND MEM_VREF VCC3V3_FLASH
nets with their own width: min track width 1.016; nets 5VS_FAN1 5VS_FAN2 +1.2V_DTH +VDISPLAY_VCC DTH_VDD12
nets with their own width: min track width 1.27; nets +5VS_HDD
nets with their own width: min track width 1.524; nets +EDPVDD +INV_PWR_SRC
nets with their own width: min track width 2.54; nets +3.3VDX_SSD

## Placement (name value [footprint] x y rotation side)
ADP100  -  [ACES_50290-00701-001_7P-T]  18.36 147.04 90 bottom
BAT100  -  [ACES_50290-01201-P01_12P-T]  26.09 78.76 180 bottom
C2  -  [C_0201]  170.6 70.29 180 top
C3  -  [C_0402]  167.44 73.17 270 top
C4  -  [C_0201]  173.43 73.42 270 top
C135  -  [C_0201]  147.28 75.96 180 top
C267  -  [C_0402]  337.24 167.33 90 top
C280  -  [C_0201]  334.55 167.51 90 top
C1031  -  [C_0201]  335.11 167.51 90 top
C1033  -  [C_0402]  335.83 167.33 90 top
C1079  -  [C_0402]  313.56 93.36 180 bottom
C1080  -  [C_0201]  311.62 100.98 180 bottom
C3003  -  [C_0201]  348.37 126.76 0 bottom
C3004  -  [C_0201]  343.71 113.39 0 bottom
C3005  -  [C_0402]  344.22 126.81 90 bottom
C3319  -  [C_0201]  304.33 80.11 0 top
C3320  -  [C_0402]  308.15 73.55 180 top
C3321  -  [C_0402]  309.3 78 0 top
CA1  -  [C_0201]  10.4 102.47 180 top
CA2  -  [C_0402]  11.79 103.65 0 top
CA3  -  [C_0201]  10.44 105.3 180 top
CA4  -  [C_0402]  10.41 104.48 180 top
CA5  -  [C_0201]  11.16 108.21 90 bottom
CA6  -  [C_0402]  11.93 108.16 90 bottom
CA7  -  [C_0402]  12.92 108.16 90 bottom
CA8  -  [C_0201]  12.9 105.05 0 bottom
CA9  -  [C_0402]  12.87 104.29 0 bottom
CA10  -  [C_0201]  11.29 106.23 270 bottom
CA11  -  [C_0402]  12.01 106.65 270 bottom
CA12  -  [C_0201]  0.84 106.95 180 top
CA13  -  [C_0402]  1.02 108.6 180 top
CA14  -  [C_0402]  1.02 107.71 180 top
CA15  -  [C_0402]  1.45 106.94 180 bottom
CA16  -  [C_0201]  0.01 106 0 bottom
CA17  -  [C_0201]  0.85 106.25 180 top
CA18  -  [C_0402]  1.45 108.29 180 bottom
CA19  -  [C_0201]  0 96.4 0 top
CA20  -  [C_0402]  1.08 109.58 90 bottom
CA21  -  [C_0402]  3.35 110.57 180 bottom
CA23  -  [C_0201]  3.02 96.34 270 bottom
CA24  -  [C_0201]  10.71 110.45 180 bottom
CA25  -  [C_0402]  10.83 111.39 90 bottom
CA26  -  [C_0201]  0.58 104.79 0 top
CA27  -  [C_0402]  0.5 104.04 270 top
CA28  -  [C_0201]  0.6 104.79 180 bottom
CA29  -  [C_0402]  0.56 104.04 270 bottom
CA30  -  [C_0402]  11.72 111.75 90 bottom
CA31  -  [C_0402]  9.24 110.39 90 bottom
CA32  -  [C_0201]  6.82 100.44 180 bottom
CA33  -  [C_0201]  2.8 100.17 180 bottom
CA34  -  [C_0201]  2.88 100.79 180 bottom
CA35  -  [C_0201]  11.43 102.13 270 top
CA36  -  [C_0201]  11.16 102.19 270 bottom
CA37  -  [C_0201]  2.44 96.32 270 bottom
CA38  -  [C_0201]  1.79 99.05 90 top
CA39  -  [C_0402]  3.4 99.65 180 top
CA40  -  [C_0201]  3.8 102.84 90 top
CA41  -  [C_0402]  4.25 125.79 180 bottom
CA42  -  [C_0402]  11.19 118.04 90 bottom
CA43  -  [C_0402]  11.73 114.01 270 top
CA44  -  [C_0402]  3.02 112.24 270 top
CA45  -  [C_0402]  5.94 110 0 top
CA77  -  [C_0402]  2.27 101.44 270 top
CA78  -  [C_0402]  7.11 99.67 180 bottom
CA119  -  [C_0402]  5.44 109.05 0 top
CA120  -  [C_0201]  2.22 99.54 0 bottom
CA121  -  [C_0201]  3.75 77.83 0 bottom
CA122  -  [C_0201]  5.38 79.01 0 bottom
CA124  -  [C_0201]  6.65 76.05 90 top
CA125  -  [C_0201]  7.29 76.05 90 top
CA126  -  [C_0201]  6.24 71.06 0 top
CA127  -  [C_0201]  9.56 72.22 0 top
CA128  -  [C_0402]  2.59 75.46 180 top
CA129  -  [C_0402]  9.45 75.15 270 top
CA130  -  [C_0201]  2.08 102.8 270 top
CA131  -  [C_0402]  84.77 79.76 180 top
CD1  -  [C_0402]  145.53 95.74 90 top
CD2  -  [C_0402]  133.65 96.72 270 top
CD3  -  [C_0402]  179.33 88.78 0 top
CD4  -  [C_0402]  179.33 87.89 0 top
CD5  -  [C_0603]  147.31 95.44 90 top
CD6  -  [C_0603]  139.37 88.79 0 top
CD7  -  [C_0603]  122.78 96.27 0 top
CD8  -  [C_0603]  136.39 96.84 270 top
CD9  -  [C_0603]  177.71 86.82 0 top
CD10  -  [C_0603]  177.71 85.62 0 top
CD11  -  [C_EEFSS0D221R]  157.11 98.32 0 top
CD12  -  [C_0402]  171.56 86.12 90 top
CD13  -  [C_0603]  172.64 85.79 90 top
CD14  -  [C_0603]  173.91 85.66 90 top
CD15  -  [C_0603]  175.18 85.66 90 top
CD16  -  [C_0402]  169.58 95.07 180 top
CD17  -  [C_0402]  169.7 93.99 180 top
CD18  -  [C_0402]  147.95 85.84 90 top
CD19  -  [C_0402]  209 88.92 90 top
CD20  -  [C_0402]  210.85 88.92 90 top
CD21  -  [C_0402]  188.66 87.33 90 top
CD22  -  [C_0402]  213.63 86.43 90 top
CD23  -  [C_0603]  214.84 96.84 270 top
CD24  -  [C_0603]  217.16 87.91 90 top
CD25  -  [C_0603]  166.59 96.68 270 top
CD26  -  [C_0603]  194.39 88.02 90 top
CD27  -  [C_0603]  242.18 97.36 270 top
CD28  -  [C_0603]  240.4 97.36 270 top
CD29  -  [C_0402]  225.13 85.74 0 top
CD30  -  [C_0402]  243.89 97.38 270 top
CD31  -  [C_0402]  244.91 97.38 270 top
CD32  -  [C_0402]  252.86 84.66 90 top
CD33  -  [C_EEFSS0D221R]  210.31 98.38 180 top
CD34  -  [C_0402]  248.48 91.46 180 top
CD35  -  [C_0402]  248.48 92.35 180 top
CD36  -  [C_0603]  266.31 88.79 180 top
CD37  -  [C_0402]  254.46 78.38 0 bottom
CD38  -  [C_0402]  266.32 86.76 180 top
CD39  -  [C_0402]  266.32 85.74 180 top
CD40  -  [C_0402]  266.19 71.65 180 top
CD41  -  [C_0402]  266.19 72.66 180 top
CD42  -  [C_0402]  254.46 77.49 0 bottom
CD43  -  [C_0402]  254.86 87.39 0 bottom
CD44  -  [C_0402]  254.86 86.51 0 bottom
CD45  -  [C_0402]  254.71 84.35 0 bottom
CD46  -  [C_0402]  254.71 83.46 0 bottom
CD51  -  [C_0402]  254.46 80.54 0 bottom
CD53  -  [C_0402]  254.46 81.43 0 bottom
CD69  -  [C_0402]  131.24 82.39 180 top
CD70  -  [C_0603]  143.42 87.64 90 top
CD71  -  [C_0603]  146.14 87.67 90 top
CD72  -  [C_0603]  138.54 96.84 270 top
CD73  -  [C_0603]  131.33 96.53 0 top
CD74  -  [C_0402]  137.12 88.23 90 top
CD75  -  [C_0402]  134.92 88.23 90 top
CD76  -  [C_0402]  132.85 87.78 90 top
CD77  -  [C_0402]  130.91 88.23 90 top
CD78  -  [C_0402]  141.32 96.72 270 top
CD79  -  [C_0402]  139.92 96.72 270 top
CD80  -  [C_0402]  221.83 95.74 90 top
CD81  -  [C_0402]  217.62 96.72 270 top
CD82  -  [C_0402]  216.22 96.72 270 top
CD83  -  [C_0402]  213.12 89.03 90 top
CD84  -  [C_0603]  225.78 87.36 90 top
CD85  -  [C_0603]  223.61 95.44 90 top
CD86  -  [C_0603]  221.95 87.2 90 top
CD87  -  [C_0603]  219.33 86.81 90 top
CD88  -  [C_0603]  254.24 80.92 0 top
CD89  -  [C_0603]  254.24 82.24 0 top
CD90  -  [C_0603]  254.24 83.51 0 top
CD3324  -  [C_0201]  90.52 70.38 0 top
CD3325  -  [C_0201]  104.75 69.4 180 bottom
CD3326  -  [C_0402]  131.24 84.22 180 top
CD3327  -  [C_0402]  131.24 83.3 180 top
CD3328  -  [C_0402]  129.34 159.02 0 top
CE2  -  [C_0402]  188.15 75.16 270 top
CE11  -  [C_0201]  156.31 72.66 0 top
CE15  -  [C_0201]  347.27 183.93 270 top
CE16  -  [C_0201]  345.82 183.93 270 top
CE17  -  [C_0402]  282.22 83.71 90 top
CE18  -  [C_0402]  296.01 73.12 0 top
CE19  -  [C_0603]  295.78 74.16 0 top
CE20  -  [C_0402]  298.27 73.81 0 top
CE22  -  [C_0603]  309.99 82.44 0 top
CE23  -  [C_0402]  307.19 83.46 0 top
CE24  -  [C_0402]  304.14 85.3 0 top
CE25  -  [C_0402]  294.74 74.41 270 top
CE26  -  [C_0402]  289.48 80.87 180 top
CE27  -  [C_0402]  304.47 74.39 270 top
CE29  -  [C_0402]  285.22 85.87 0 top
CE30  -  [C_0402]  286.13 81.81 180 top
CE31  -  [C_0402]  304.14 86.19 0 top
CE32  -  [C_0402]  289.48 82.64 270 top
CE33  -  [C_0402]  289.48 85.44 270 top
CE34  -  [C_0402]  301.04 91.94 90 top
CE35  -  [C_0402]  288.09 84.17 270 top
CE36  -  [C_0402]  288.09 86.96 270 top
CE37  -  [C_0402]  288.69 70.78 180 top
CE38  -  [C_0402]  290.4 71.65 270 top
CE39  -  [C_0402]  302.95 92.02 90 top
CE40  -  [C_0603]  302.31 74.38 270 top
CE41  -  [C_0402]  286 87.9 180 top
CE42  -  [C_0402]  288.28 76.53 270 top
CE43  -  [C_0201]  288.28 77.39 90 top
CE44  -  [C_0402]  296.93 89.45 180 top
CE45  -  [C_0402]  113.33 183.36 270 bottom
CE46  -  [C_0402]  173.2 187.47 180 bottom
CE47  -  [C_0402]  186.77 115.44 0 top
CE48  -  [C_0402]  291.83 99.34 270 top
CE49  -  [C_0402]  179.77 115.97 90 bottom
CE50  -  [C_0402]  279.65 92.6 180 bottom
CE51  -  [C_0402]  298.68 89.12 90 top
CE52  -  [C_0402]  301.26 74.27 270 top
CE65  -  [C_0402]  191.43 76.07 0 top
CE66  -  [C_0402]  101.04 101.2 0 top
CE67  -  [C_0402]  332.79 114.93 270 bottom
CE68  -  [C_0402]  27.38 117.47 90 bottom
CE69  -  [C_0402]  156.09 139.27 0 top
CE70  -  [C_0402]  284.72 80.61 270 top
CE71  -  [C_0402]  282.7 81.49 180 top
CE72  -  [C_0402]  239.14 173.5 180 bottom
CE73  -  [C_0402]  152.2 78.38 270 bottom
CE74  -  [C_0402]  152.2 76.6 270 bottom
CE75  -  [C_0201]  156.31 76.22 0 top
CE76  -  [C_0603]  155.94 77.13 0 top
CE77  -  [C_0402]  190.93 80.16 0 bottom
CE78  -  [C_0402]  190.04 80.16 180 bottom
CE79  -  [C_0402]  185.61 80.1 90 bottom
CE80  -  [C_0402]  184.66 80.1 90 bottom
CE81  -  [C_0402]  162.92 75.84 0 bottom
CE82  -  [C_0402]  162.92 76.73 0 bottom
CE83  -  [C_0603]  151.21 73.67 180 bottom
CE84  -  [C_0201]  147.57 72.03 180 top
CE85  -  [C_0201]  147.59 72.8 180 top
CE1501  -  [C_0402]  294.69 71.44 0 top
CE3319  -  [C_0402]  276.19 80.84 180 top
CE3321  -  [C_0402]  147.28 77.41 180 bottom
CE3322  -  [C_0402]  149.14 75.13 90 bottom
CE3323  -  [C_0402]  200.33 118.69 90 top
CF1  -  [C_0603]  238.2 113.06 270 top
CF2  -  [C_0402]  237.67 115.33 90 top
CH3  -  [C_0402]  121.21 163.77 90 bottom
CH5  -  [C_0201]  185.76 150.22 0 bottom
CH6  -  [C_0201]  185.76 150.86 0 bottom
CH7  -  [C_0201]  185.75 148.16 0 bottom
CH8  -  [C_0201]  185.75 148.8 0 bottom
CH9  -  [C_0201]  187.21 146.89 0 bottom
CH10  -  [C_0201]  187.21 147.53 0 bottom
CH11  -  [C_0201]  185.75 146.41 0 bottom
CH12  -  [C_0201]  185.75 145.78 0 bottom
CH13  -  [C_0201]  187.21 144.54 0 bottom
CH14  -  [C_0201]  187.21 145.18 0 bottom
CH15  -  [C_0201]  185.94 144.1 0 bottom
CH16  -  [C_0201]  185.94 143.46 0 bottom
CH17  -  [C_0201]  187.78 142.64 0 bottom
CH18  -  [C_0201]  187.78 143.27 0 bottom
CH19  -  [C_0201]  186.32 141.62 0 bottom
CH20  -  [C_0201]  186.32 142.26 0 bottom
CH21  -  [C_0201]  187.78 141.24 0 bottom
CH22  -  [C_0201]  187.78 140.61 0 bottom
CH23  -  [C_0201]  186.39 139.65 0 bottom
CH24  -  [C_0201]  186.39 140.29 0 bottom
CH25  -  [C_0201]  187.78 139.21 0 bottom
CH26  -  [C_0201]  187.78 138.58 0 bottom
CH27  -  [C_0201]  186.39 137.5 0 bottom
CH28  -  [C_0201]  186.39 138.13 0 bottom
CH29  -  [C_0201]  187.78 137.11 0 bottom
CH30  -  [C_0201]  187.78 136.48 0 bottom
CH31  -  [C_0201]  186.45 134.96 0 bottom
CH32  -  [C_0201]  186.45 135.59 0 bottom
CH33  -  [C_0201]  187.85 134.45 0 bottom
CH34  -  [C_0201]  187.85 133.81 0 bottom
CH35  -  [C_0201]  187.08 132.27 0 bottom
CH36  -  [C_0201]  187.08 132.9 0 bottom
CH44  -  [C_0201]  278.75 72.03 0 top
CH45  -  [C_0201]  67.94 71.39 180 bottom
CH46  -  [C_0201]  68.94 71.39 0 bottom
CH47  -  [C_0201]  101.14 83.97 270 top
CH48  -  [C_0201]  101.14 84.56 90 top
CH50  -  [C_0201]  103.02 69.77 180 bottom
CH51  -  [C_0201]  104.17 70.01 0 bottom
CH52  -  [C_0402]  69.6 73.17 180 top
CH53  -  [C_0402]  73.2 72.84 270 top
CH70  -  [C_0201]  71.53 71.33 180 top
CH80  -  [C_0201]  71.98 68.7 180 top
CH82  -  [C_0201]  88.06 72.95 270 top
CH92  -  [C_0402]  92.35 80.92 270 top
CH100  -  [C_0402]  229.07 87.58 270 top
CH101  -  [C_0402]  122.64 86.62 270 top
CH102  -  [C_0402]  170.91 138.51 270 top
CH103  -  [C_0402]  170.94 140.32 270 top
CH104  -  [C_0402]  169.53 138.59 270 top
CH105  -  [C_0402]  172.63 148.34 0 top
CH106  -  [C_0402]  172.21 149.84 45 top
CH107  -  [C_0402]  170.71 145.74 0 top
CH108  -  [C_0402]  170.86 146.64 0 top
CH109  -  [C_0402]  170.87 143.66 270 top
CH110  -  [C_0402]  170.71 144.85 0 top
CH111  -  [C_0402]  168.85 146.92 180 top
CH112  -  [C_0402]  172.33 155.01 180 top
CH113  -  [C_0402]  171.37 153.21 90 top
CH114  -  [C_0402]  175.67 154.82 0 top
CH115  -  [C_0402]  168.94 153.67 180 top
CH116  -  [C_0402]  170.46 153.2 90 top
CH117  -  [C_0402]  175.91 153.1 0 top
CH118  -  [C_0402]  147.42 133.5 0 top
CH119  -  [C_0402]  158.25 129.17 90 top
CH120  -  [C_0402]  168.1 129.41 270 top
CH121  -  [C_0402]  147.45 131.7 0 top
CH122  -  [C_0402]  154.86 134.49 90 top
CH123  -  [C_0402]  160.36 129.04 90 top
CH124  -  [C_0402]  147.42 132.61 0 top
CH125  -  [C_0402]  156.6 135.16 0 top
CH126  -  [C_0402]  165.57 129.41 270 top
CH127  -  [C_0402]  167.19 134.43 0 top
CH128  -  [C_0402]  171.42 130.97 0 top
CH129  -  [C_0603]  172.64 128.58 90 top
CH130  -  [C_0603]  175.06 128.99 90 top
CH131  -  [C_0603]  176.33 128.61 90 top
CH132  -  [C_0603]  170.62 128.62 90 top
CH133  -  [C_0201]  168.5 152.93 180 top
CH134  -  [C_0603]  168.55 155.02 180 top
CH135  -  [C_0603]  168.79 151.41 180 top
CH136  -  [C_0805]  170.4 159.09 90 bottom
CH138  -  [C_0805]  172.17 159.09 90 bottom
CH174  -  [C_0402]  128.23 161.84 270 top
CH175  -  [C_0402]  122.73 164.53 90 bottom
CH176  -  [C_0402]  83.74 81.43 0 top
CH177  -  [C_0402]  99.17 87.14 0 bottom
CH178  -  [C_0402]  99.19 86.2 0 bottom
CH179  -  [C_0201]  99.67 88.28 0 bottom
CH180  -  [C_0201]  68.76 92.57 270 bottom
CH181  -  [C_0402]  69.77 94.32 90 bottom
CH182  -  [C_0402]  68.54 94.27 90 bottom
CH183  -  [C_0201]  85.36 84.31 270 top
CH184  -  [C_0402]  87.76 84.64 270 top
CH187  -  [C_0201]  92.46 74.27 90 top
CH188  -  [C_0201]  64.9 84.85 180 top
CH189  -  [C_0201]  77.79 86.06 180 top
CH190  -  [C_0201]  77.42 83.03 90 top
CH191  -  [C_0201]  98.09 69.23 180 top
CH192  -  [C_0201]  86.19 86.96 90 top
CH196  -  [C_0201]  278.75 71.39 0 top
CH197  -  [C_0402]  119.14 120.38 180 top
CH198  -  [C_0402]  78.66 71.95 90 top
CH200  -  [C_0201]  91.11 72.87 270 top
CH201  -  [C_0402]  84.57 84.45 270 top
CH202  -  [C_0402]  100.13 94.57 270 bottom
CH203  -  [C_0201]  99.02 92.52 0 top
CH204  -  [C_0201]  88.7 72.95 270 top
CH205  -  [C_0201]  93.09 80.68 270 top
CH206  -  [C_0402]  84.38 82.52 0 top
CH207  -  [C_0201]  96.94 93.66 180 top
CH3320  -  [C_0201]  90.47 72.81 270 top
CH3321  -  [C_0201]  85.4 76.94 270 top
CH3322  -  [C_0201]  99.02 91.94 0 top
CH3323  -  [C_0201]  100.56 91.29 90 top
CH3324  -  [C_0201]  88.91 84.89 270 top
CH3327  -  [C_0402]  62.29 72.54 90 top
CH3329  -  [C_0201]  72.72 68.17 180 bottom
CH3331  -  [C_0201]  72.72 69.94 90 top
CH3332  -  [C_0201]  171.11 132.47 270 top
CH3333  -  [C_0201]  140.73 134.96 0 top
CH3334  -  [C_0402]  178.88 146.96 180 top
CI1  -  [C_0402]  25.45 162.61 90 top
CI2  -  [C_0402]  328.22 127.79 270 bottom
CI3  -  [C_0402]  324.03 100.04 270 top
CI4  -  [C_0402]  316.92 104.59 90 top
CI5  -  [C_0402]  322.25 106.83 270 top
CI6  -  [C_0402]  321.11 106.83 270 top
CI7  -  [C_0402]  319.96 106.83 270 top
CI8  -  [C_0402]  318.95 106.83 270 top
CI9  -  [C_0201]  20.19 173.37 180 bottom
CI10  -  [C_0201]  20.19 172.48 180 bottom
CI11  -  [C_0805]  18.02 175.32 90 top
CI12  -  [C_0603]  16.56 175.21 270 top
CI13  -  [C_0402]  16.62 176.54 90 top
CI16  -  [C_0402]  321.61 98.82 270 top
CI17  -  [C_0805]  329.2 136.67 180 bottom
CI18  -  [C_0603]  328.79 135.15 180 bottom
CI19  -  [C_0402]  328.87 134.07 180 bottom
CI20  -  [C_0402]  322.5 98.82 270 top
CI21  -  [C_0402]  17.2 171.01 90 bottom
CI22  -  [C_0402]  322.4 120.68 90 top
CLRP1  -  [SHORTPADS]  64.95 71.27 180 bottom
CM1  -  [C_0201]  25.45 144.89 90 bottom
CM2  -  [C_0402]  22.99 143.07 90 bottom
CM3  -  [C_0201]  22.22 143.69 270 bottom
CM4  -  [C_0201]  21.35 137.69 0 bottom
CM5  -  [C_0201]  20.88 143.69 270 bottom
CM6  -  [C_0201]  17.2 135.65 270 top
CM7  -  [C_0201]  17.83 135.65 270 top
CM8  -  [C_0201]  15.11 134.61 180 bottom
CM9  -  [C_0402]  18.77 138.58 0 bottom
CM10  -  [C_0201]  19.52 137.23 180 bottom
CM11  -  [C_0201]  20.41 136.31 180 bottom
CM12  -  [C_0201]  20.41 135.76 180 bottom
CM13  -  [C_0201]  18.94 137.81 0 bottom
CM14  -  [C_0201]  19.23 135.65 270 top
CM15  -  [C_0201]  19.86 135.65 270 top
CM16  -  [C_0201]  20.62 135.69 270 top
CM17  -  [C_0201]  21.26 135.69 270 top
CM18  -  [C_0201]  22.15 135.65 270 top
CM19  -  [C_0201]  22.78 135.65 270 top
CM20  -  [C_0201]  15.62 136.92 180 top
CM21  -  [C_0201]  15.62 137.51 180 top
CM22  -  [C_0201]  15.71 143.15 180 bottom
CM23  -  [C_0402]  18.85 143.32 90 bottom
CM24  -  [C_0201]  20.19 144.07 270 bottom
CM25  -  [C_0201]  19.61 143.49 90 bottom
CM26  -  [C_0201]  21.74 135.41 90 bottom
CM27  -  [C_0402]  24.74 135.27 0 bottom
CM28  -  [C_0201]  25.62 140.23 180 bottom
CM29  -  [C_0201]  25.55 136.23 180 bottom
CM30  -  [C_0201]  25.62 139.46 180 bottom
CM31  -  [C_0201]  24.97 136.99 0 bottom
CM32  -  [C_0201]  24.97 138.45 0 bottom
CM33  -  [C_0201]  25.03 140.86 0 bottom
CM34  -  [C_0402]  17.4 141.37 180 bottom
CM35  -  [C_0201]  16.65 140.61 0 bottom
CM37  -  [C_0201]  15.11 135.21 180 bottom
CM38  -  [C_0201]  16.52 138.83 0 bottom
CM39  -  [C_0201]  18.05 140.1 0 bottom
CM40  -  [C_0201]  18.54 161.94 180 bottom
CM41  -  [C_0201]  17.96 133.75 270 top
CM43  -  [C_0402]  14.07 140.55 270 top
CM44  -  [C_0402]  14.05 141.46 90 top
CM45  -  [C_0201]  13.91 137.46 180 top
CM46  -  [C_0201]  13.91 138.09 180 top
CM50  -  [C_0201]  17.11 139.46 180 bottom
CN1  -  [C_0603]  333.36 165.1 0 top
CN2  -  [C_0402]  333.88 164.06 0 top
CN6  -  [C_0603]  345.19 154.59 0 top
CN7  -  [C_0402]  344.21 154.75 180 top
CN8  -  [C_0402]  333.91 166.17 0 top
CN9  -  [C_0201]  334.35 166.92 0 top
CN20  -  [C_0201]  329.2 147.85 0 bottom
CN21  -  [C_0201]  329.2 146.96 0 bottom
CN22  -  [C_0402]  334.87 171.98 0 top
CR1  -  [C_0201]  332.41 104.12 90 bottom
CR2  -  [C_0201]  333.55 105.47 270 bottom
CR3  -  [C_0402]  335.31 107.99 90 bottom
CR4  -  [C_0603]  330.7 104.16 180 bottom
CR5  -  [C_0201]  333.74 100.68 270 bottom
CR6  -  [C_0603]  330.7 105.36 180 bottom
CR7  -  [C_0402]  339.14 99.76 90 bottom
CR8  -  [C_0201]  332.92 108.93 270 bottom
CR9  -  [C_0402]  338.25 99.76 90 bottom
CR10  -  [C_0402]  336.47 99.76 90 bottom
CR11  -  [C_0201]  342.32 104.82 90 bottom
CR12  -  [C_0402]  343.08 104.4 90 bottom
CR13  -  [C_0402]  335.52 99.76 90 bottom
CR14  -  [C_0603]  325.89 117.17 270 top
CR15  -  [C_0201]  325.89 118.11 90 top
CR16  -  [C_0402]  341.11 106.88 90 bottom
CR17  -  [C_0603]  347.54 113.56 0 bottom
CR18  -  [C_0402]  347.95 112.16 0 bottom
CS12  -  [C_0402]  235.83 79.7 90 bottom
CS13  -  [C_0402]  236.78 79.7 90 bottom
CS14  -  [C_0402]  236.45 77.87 0 top
CS15  -  [C_0603]  237.86 79.46 90 bottom
CS17  -  [C_0201]  231.03 79.91 270 bottom
CS18  -  [C_0201]  231.67 79.91 270 bottom
CS19  -  [C_0201]  233.19 79.91 270 bottom
CS20  -  [C_0201]  232.56 79.91 270 bottom
CT1  -  [C_0201]  22.26 99.23 90 bottom
CT2  -  [C_0201]  23.5 99.75 270 bottom
CT3  -  [C_0201]  22.83 99.23 90 bottom
CT4  -  [C_0201]  24.05 99.75 270 bottom
CT5  -  [C_0201]  24.64 99.22 90 bottom
CT6  -  [C_0201]  25.88 99.8 270 bottom
CT7  -  [C_0201]  25.2 99.22 90 bottom
CT8  -  [C_0201]  26.45 99.8 270 bottom
CT17  -  [C_0201]  32.52 109.75 0 bottom
CT18  -  [C_0201]  32.52 109.11 0 bottom
CT19  -  [C_0201]  33.22 107.33 0 bottom
CT20  -  [C_0201]  33.22 107.97 0 bottom
CT21  -  [C_0201]  31.89 106.44 0 bottom
CT22  -  [C_0201]  31.89 107.08 0 bottom
CT23  -  [C_0201]  33.54 105.48 0 bottom
CT24  -  [C_0201]  33.54 106.06 0 bottom
CT25  -  [C_0201]  31.13 106.7 0 top
CT26  -  [C_0201]  31.13 107.27 0 top
CT29  -  [C_0201]  32.27 104.35 0 bottom
CT30  -  [C_0201]  32.27 104.98 0 bottom
CT31  -  [C_0201]  34 103.22 0 bottom
CT32  -  [C_0201]  34 103.85 0 bottom
CT33  -  [C_0201]  35.57 101.75 0 bottom
CT34  -  [C_0201]  35.57 102.38 0 bottom
CT35  -  [C_0201]  33.54 100.78 0 bottom
CT36  -  [C_0201]  33.54 101.36 0 bottom
CT37  -  [C_0201]  16.4 105.2 180 bottom
CT38  -  [C_0201]  16.4 105.77 180 bottom
CT39  -  [C_0201]  17.79 103.76 180 bottom
CT40  -  [C_0201]  17.79 104.34 180 bottom
CT41  -  [C_0201]  31.38 104.86 0 top
CT42  -  [C_0201]  31.38 104.29 0 top
CT43  -  [C_0201]  19.86 99.08 90 bottom
CT44  -  [C_0201]  19.86 98.44 270 bottom
CT47  -  [C_0201]  38.18 90.76 90 top
CT50  -  [C_0201]  32.4 108.93 270 top
CT52  -  [C_0201]  16.77 112.47 90 bottom
CT53  -  [C_0402]  15.75 109.54 0 bottom
CT54  -  [C_0402]  15.76 108.64 0 bottom
CT55  -  [C_0402]  17.51 112.07 90 bottom
CT56  -  [C_0402]  15.74 110.44 0 bottom
CT62  -  [C_0201]  24.36 111.56 90 top
CT63  -  [C_0201]  25.79 109.62 0 top
CT64  -  [C_0201]  24.94 111.56 90 top
CT65  -  [C_0201]  24.98 106.17 180 top
CT66  -  [C_0201]  28.41 104.18 180 top
CT67  -  [C_0201]  29.51 104.07 270 top
CT68  -  [C_0201]  30.15 104.07 270 top
CT71  -  [C_0201]  26.15 101.78 270 top
CT72  -  [C_0201]  26.81 101.94 0 top
CT74  -  [C_0201]  20.03 109.42 180 top
CT80  -  [C_0201]  23.86 101.78 270 top
CT81  -  [C_0201]  25.01 101.78 270 top
CT82  -  [C_0201]  25.58 101.78 270 top
CT83  -  [C_0201]  20.03 108.83 180 top
CT84  -  [C_0201]  20.03 110 180 top
CT85  -  [C_0201]  20.03 107.66 180 top
CT86  -  [C_0201]  20.03 108.25 180 top
CT88  -  [C_0603]  21.37 111.54 180 top
CT89  -  [C_0603]  21.01 112.73 90 top
CT90  -  [C_0603]  19.93 114.06 180 top
CT93  -  [C_0201]  26.31 103.55 180 top
CT94  -  [C_0201]  26.56 104.16 0 top
CT95  -  [C_0402]  19.82 104.5 180 top
CT96  -  [C_0402]  19.81 103.59 180 top
CT97  -  [C_0402]  19.82 106.29 180 top
CT98  -  [C_0402]  19.82 105.4 180 top
CT99  -  [C_0201]  23.25 104.23 270 top
CT100  -  [C_0201]  23.23 104.86 90 top
CT101  -  [C_0201]  29.55 110.13 180 top
CT102  -  [C_0201]  30.06 108.86 180 top
CT103  -  [C_0201]  30.09 109.48 180 top
CT107  -  [C_0201]  31.13 105.49 0 top
CT108  -  [C_0201]  31.13 106.06 0 top
CT120  -  [C_0402]  9.77 133.89 270 bottom
CT121  -  [C_0402]  8.88 133.89 270 bottom
CT122  -  [C_0402]  5.83 132.05 270 bottom
CT123  -  [C_0402]  10.13 130.59 270 bottom
CT141  -  [C_0201]  20 110.56 180 top
CT142  -  [C_0201]  20.03 107.08 180 top
CT143  -  [C_0201]  22.06 108.22 180 top
CT144  -  [C_0402]  14.4 124.99 90 bottom
CT145  -  [C_0201]  19.6 126.66 0 top
CT146  -  [C_0402]  18.21 125.44 270 top
CT147  -  [C_0603]  26.15 121.18 0 bottom
CT148  -  [C_0603]  26.15 122.45 0 bottom
CT149  -  [C_0603]  26.74 123.52 90 bottom
CT150  -  [C_0603]  25.53 123.52 90 bottom
CT151  -  [C_0402]  16.95 127.78 180 bottom
CT152  -  [C_0402]  18.59 120.16 270 bottom
CT153  -  [C_0603]  23.83 132.52 180 bottom
CT157  -  [C_0603]  24.97 127.03 0 bottom
CT158  -  [C_0402]  20.83 125.37 0 top
CT159  -  [C_0402]  23.1 128.91 90 top
CT160  -  [C_0402]  24.65 128.91 90 top
CT163  -  [C_0201]  26.2 106.11 180 top
CT164  -  [C_0603]  29.01 101.75 0 top
CT165  -  [C_0603]  29.01 100.48 0 top
CT174  -  [C_0201]  28.92 99.79 270 bottom
CT175  -  [C_0201]  28.33 99.79 270 bottom
CT176  -  [C_0201]  32.02 99.54 0 bottom
CT177  -  [C_0201]  32.02 100.09 0 bottom
CT178  -  [C_0201]  27.08 99.22 90 bottom
CT179  -  [C_0201]  33.74 98.39 180 bottom
CT180  -  [C_0201]  27.66 99.22 90 bottom
CT181  -  [C_0201]  33.74 98.95 180 bottom
CT182  -  [C_0201]  18.95 113.31 180 bottom
CT183  -  [C_0201]  18.95 113.89 180 bottom
CT184  -  [C_0201]  21.26 104.26 270 top
CT185  -  [C_0201]  20.56 103.12 270 top
CT186  -  [C_0201]  21.13 113.3 0 bottom
CT187  -  [C_0201]  21.13 113.87 0 bottom
CT188  -  [C_0603]  26.15 119.91 0 bottom
CT189  -  [C_0402]  13.45 118.31 90 bottom
CV156  -  [C_0402]  49.66 96.16 180 top
CV157  -  [C_0603]  49.9 95.01 180 top
CV158  -  [C_0201]  60.38 94.39 90 bottom
CV159  -  [C_0201]  61.01 94.39 90 bottom
CV160  -  [C_0201]  62.66 94.39 90 bottom
CV161  -  [C_0201]  63.3 94.39 90 bottom
CV162  -  [C_0201]  63.93 94.39 90 bottom
CV163  -  [C_0201]  64.57 94.39 90 bottom
CV164  -  [C_0201]  65.33 94.39 90 bottom
CV165  -  [C_0201]  65.96 94.39 90 bottom
CV166  -  [C_0201]  59.74 94.39 90 bottom
CV167  -  [C_0201]  59.11 94.39 90 bottom
CV168  -  [C_0402]  40.18 100.91 90 top
CV169  -  [C_0402]  43.94 102.63 180 top
CV178  -  [C_0201]  12.4 158.07 90 top
CV179  -  [C_0402]  13.16 158.03 90 top
CV180  -  [C_0201]  12.37 160.08 270 top
CV181  -  [C_0201]  12.46 144.46 180 bottom
CV182  -  [C_0201]  13.11 144.03 90 bottom
CV183  -  [C_0402]  52.93 96.77 180 bottom
CV184  -  [C_0402]  51.46 95.84 270 bottom
CV499  -  [C_0402]  243.65 114.74 90 top
CV794  -  [C_0402]  233.35 119.07 90 top
CV796  -  [C_0402]  234.24 119.07 90 top
CV798  -  [C_0603]  235.38 118.95 90 top
CV817  -  [C_0402]  206.4 118.36 0 top
CV818  -  [C_0201]  189.18 132.64 180 top
CV819  -  [C_0201]  189.18 132.01 180 top
CV820  -  [C_0201]  190.84 133.66 180 top
CV821  -  [C_0201]  190.84 133.02 180 top
CV822  -  [C_0201]  189.18 134.04 180 top
CV823  -  [C_0201]  189.18 134.67 180 top
CV824  -  [C_0201]  190.84 135.69 180 top
CV825  -  [C_0201]  190.84 135.05 180 top
CV826  -  [C_0201]  189.18 136.07 180 top
CV827  -  [C_0201]  189.18 136.7 180 top
CV828  -  [C_0201]  190.84 137.72 180 top
CV829  -  [C_0201]  190.84 137.09 180 top
CV830  -  [C_0201]  189.18 138.1 180 top
CV831  -  [C_0201]  189.18 138.74 180 top
CV832  -  [C_0201]  190.84 139.75 180 top
CV833  -  [C_0201]  190.84 139.12 180 top
CV834  -  [C_0201]  189.18 140.77 180 top
CV835  -  [C_0201]  189.18 140.13 180 top
CV836  -  [C_0201]  190.84 141.15 180 top
CV837  -  [C_0201]  190.84 141.78 180 top
CV838  -  [C_0201]  189.18 142.8 180 top
CV839  -  [C_0201]  189.18 142.17 180 top
CV840  -  [C_0201]  191.79 143.75 180 top
CV841  -  [C_0201]  191.79 143.12 180 top
CV842  -  [C_0201]  190.26 144.83 180 top
CV843  -  [C_0201]  190.26 144.2 180 top
CV844  -  [C_0201]  191.79 145.85 180 top
CV845  -  [C_0201]  191.79 145.21 180 top
CV846  -  [C_0201]  190.26 146.17 180 top
CV847  -  [C_0201]  190.26 146.8 180 top
CV848  -  [C_0201]  191.79 147.18 180 top
CV849  -  [C_0201]  191.79 147.82 180 top
CV850  -  [C_0402]  218 145.85 0 top
CV851  -  [C_0402]  202.15 131.49 0 top
CV852  -  [C_0402]  198.8 130.26 270 top
CV853  -  [C_0402]  224.94 113.96 0 top
CV854  -  [C_0402]  199.66 128.49 180 top
CV855  -  [C_0402]  198.93 121.56 0 bottom
CV856  -  [C_0402]  198.93 122.83 0 bottom
CV857  -  [C_0201]  215.91 118.51 0 top
CV858  -  [C_0201]  215.23 118.51 180 top
CV859  -  [C_0402]  197.41 141.69 180 top
CV860  -  [C_0402]  198.21 139.91 180 top
CV861  -  [C_0603]  222.62 184.04 0 top
CV862  -  [C_0402]  224.9 127.78 270 bottom
CV863  -  [C_0603]  218.87 155.21 270 top
CV864  -  [C_0603]  216.2 154.89 0 top
CV865  -  [C_0402]  198.12 144.16 180 top
CV866  -  [C_0402]  192.47 128.45 90 top
CV867  -  [C_0603]  222.62 182.8 0 top
CV868  -  [C_0603]  220.12 185.21 270 bottom
CV869  -  [C_0603]  194.3 153.69 90 top
CV870  -  [C_0603]  219.41 147.26 0 top
CV871  -  [C_0402]  223.51 127.78 270 bottom
CV872  -  [C_0603]  220.01 148.93 0 top
CV873  -  [C_0603]  220.21 153.5 90 top
CV874  -  [C_0402]  199.48 135.56 0 top
CV875  -  [C_0402]  199.8 143.49 0 top
CV876  -  [C_0402]  199.62 137.5 0 top
CV877  -  [C_0402]  199.62 138.45 0 top
CV878  -  [C_0603]  191.63 149.9 180 top
CV879  -  [C_0603]  195.26 151.31 90 top
CV880  -  [C_0603]  190.22 148.7 0 top
CV881  -  [C_0603]  198.29 141.89 0 top
CV882  -  [C_0603]  197.28 150.73 0 top
CV883  -  [C_0603]  199.3 147.29 270 top
CV884  -  [C_0603]  212.66 133.99 270 top
CV885  -  [C_0402]  214.56 136.47 270 top
CV886  -  [C_0402]  202.13 148.27 180 top
CV887  -  [C_0402]  203.68 146.5 90 top
CV888  -  [C_0402]  213.74 134.13 270 top
CV889  -  [C_0402]  205.22 146.56 90 top
CV890  -  [C_0402]  202.2 145.85 180 top
CV891  -  [C_0402]  196.71 133.29 90 top
CV892  -  [C_0402]  212.17 131.23 180 top
CV893  -  [C_0402]  219.44 129.72 0 top
CV894  -  [C_0402]  219.32 131.23 90 top
CV895  -  [C_0603]  217.79 130.62 90 top
CV896  -  [C_0603]  221.77 131.07 270 top
CV897  -  [C_0603]  223.06 131.07 270 top
CV898  -  [C_0402]  200.38 145.81 270 top
CV899  -  [C_0402]  221.28 154.89 270 top
CV900  -  [C_0402]  215.99 141.27 90 top
CV901  -  [C_0402]  208.64 146.64 90 top
CV902  -  [C_0402]  210.92 146.64 0 top
CV903  -  [C_0402]  207.9 145.79 180 top
CV904  -  [C_0402]  209.51 130.63 90 top
CV905  -  [C_0402]  210.4 130.63 90 top
CV906  -  [C_0402]  210.92 119.4 0 top
CV907  -  [C_0603]  209.92 119.27 180 top
CV917  -  [C_0402]  171.31 179.86 180 top
CV918  -  [C_0402]  172.96 177.09 0 top
CV919  -  [C_0402]  164.78 183.09 180 top
CV920  -  [C_0402]  245.67 118.81 90 top
CV921  -  [C_0402]  206.11 146.78 270 top
CV922  -  [C_0402]  213.73 139.04 270 top
CV923  -  [C_0402]  212.53 145.75 180 top
CV924  -  [C_0603]  190.39 151.92 0 top
CV925  -  [C_0201]  237.24 172.61 180 top
CV926  -  [C_0402]  202.3 172.66 90 top
CV927  -  [C_0402]  222.35 176.45 90 top
CV928  -  [C_0201]  197.15 168.89 90 top
CV929  -  [C_0402]  206.81 167.23 270 top
CV930  -  [C_0402]  206.16 176.1 0 top
CV931  -  [C_0402]  208.52 174.34 270 top
CV932  -  [C_0402]  202.23 177.68 90 top
CV933  -  [C_0402]  201.89 162.6 180 bottom
CV934  -  [C_0402]  202.97 162.57 0 bottom
CV935  -  [C_0402]  206.93 175.23 270 top
CV936  -  [C_0402]  204.72 174.15 180 top
CV937  -  [C_0603]  236.72 177.63 90 top
CV938  -  [C_0603]  234.45 179.55 180 top
CV939  -  [C_0603]  238.12 164.81 90 top
CV940  -  [C_0603]  224.97 164.8 180 top
CV941  -  [C_0603]  237.22 169.18 270 top
CV942  -  [C_0603]  230.05 176.62 90 top
CV943  -  [C_0603]  231.36 176.63 90 top
CV944  -  [C_0603]  222.44 179.79 90 top
CV945  -  [C_0603]  221.23 179.79 90 top
CV946  -  [C_0603]  223.65 179.79 90 top
CV947  -  [C_0603]  224.84 179.79 90 top
CV948  -  [C_0402]  231.2 172.93 180 top
CV949  -  [C_0402]  227.19 173.31 0 top
CV950  -  [C_0402]  230.17 175.42 270 top
CV951  -  [C_0402]  235.45 179.2 90 top
CV952  -  [C_0402]  226.54 174.68 0 top
CV953  -  [C_0402]  236.08 169.19 270 top
CV954  -  [C_0402]  237.16 173.55 90 top
CV955  -  [C_0402]  237.01 165.32 90 top
CV956  -  [C_0402]  237.16 176.5 270 top
CV957  -  [C_0402]  234.54 172.99 0 top
CV958  -  [C_0603]  215.95 178.01 270 top
CV959  -  [C_0603]  202.49 179.66 90 top
CV960  -  [C_0603]  214.62 178.01 270 top
CV961  -  [C_0603]  214.3 171.91 0 top
CV962  -  [C_0603]  209.15 177.08 90 top
CV963  -  [C_0603]  209.16 179.66 90 top
CV964  -  [C_0603]  207.82 179.66 90 top
CV965  -  [C_0603]  207.75 177.08 90 top
CV966  -  [C_0603]  205.16 179.66 90 top
CV967  -  [C_0603]  203.82 179.66 90 top
CV968  -  [C_0603]  206.49 179.66 90 top
CV969  -  [C_0402]  212.57 177.95 0 top
CV970  -  [C_0402]  211.63 177.3 90 top
CV971  -  [C_0402]  213.58 164.48 180 top
CV972  -  [C_0402]  212.79 173.94 0 top
CV973  -  [C_0402]  213.47 167.58 90 top
CV974  -  [C_0402]  213.47 165.74 90 top
CV975  -  [C_0402]  205.09 178.52 0 top
CV976  -  [C_0402]  204.08 178.64 180 top
CV977  -  [C_0402]  202.23 175.8 270 top
CV978  -  [C_0402]  214.57 175.49 270 top
CV979  -  [C_0402]  231.32 174.31 90 top
CV980  -  [C_0402]  225.55 173.74 90 top
CV981  -  [C_0402]  223.89 175.58 90 top
CV982  -  [C_0402]  223.89 177.42 90 top
CV983  -  [C_0402]  228.9 166.26 270 top
CV984  -  [C_0402]  234.59 176.53 0 top
CV985  -  [C_0402]  236.12 165.04 180 top
CV986  -  [C_0402]  224.98 166.01 180 top
CV987  -  [C_0201]  240.94 122.34 180 top
CV988  -  [C_0402]  239.29 157.74 180 top
CV989  -  [C_0402]  244.81 162.59 0 top
CV990  -  [C_0201]  241 158.32 0 top
CV991  -  [C_0402]  245.25 149.61 90 top
CV992  -  [C_0402]  248.35 148.23 180 top
CV993  -  [C_0402]  244.83 153.93 0 top
CV994  -  [C_0402]  236.63 157.75 0 top
CV995  -  [C_0402]  235.32 146.58 180 top
CV996  -  [C_0402]  247.5 156.23 0 top
CV997  -  [C_0402]  235.76 157.76 90 top
CV998  -  [C_0402]  246.57 145.94 180 top
CV999  -  [C_0603]  244.53 123.16 0 top
CV1000  -  [C_0603]  244.27 128.43 0 top
CV1001  -  [C_0603]  232.78 122.26 270 top
CV1002  -  [C_0603]  245.86 134.7 180 top
CV1003  -  [C_0603]  246.94 134.7 0 top
CV1004  -  [C_0603]  247.76 124.8 90 top
CV1005  -  [C_0603]  247 130.07 0 top
CV1006  -  [C_0603]  247 128.67 0 top
CV1007  -  [C_0603]  243.76 126.66 0 top
CV1008  -  [C_0603]  244.21 121.3 0 top
CV1009  -  [C_0603]  247 127.4 0 top
CV1010  -  [C_0402]  243.33 128.61 180 top
CV1011  -  [C_0402]  233.92 122.4 270 top
CV1012  -  [C_0402]  236.91 122.4 270 top
CV1013  -  [C_0402]  248.4 149.67 90 top
CV1014  -  [C_0402]  237.79 122.4 270 top
CV1015  -  [C_0402]  245.88 131.96 0 top
CV1016  -  [C_0402]  235.76 122.4 270 top
CV1017  -  [C_0402]  234.81 122.4 270 top
CV1018  -  [C_0402]  241.73 132.92 0 top
CV1019  -  [C_0402]  237.72 134.51 0 top
CV1020  -  [C_0603]  245.03 158.77 90 top
CV1021  -  [C_0603]  233.79 157.82 90 top
